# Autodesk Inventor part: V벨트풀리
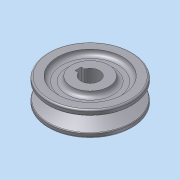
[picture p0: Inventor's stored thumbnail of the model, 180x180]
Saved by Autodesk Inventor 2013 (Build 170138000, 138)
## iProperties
Created: 2015-03
Part Number: V벨트풀리
Material: 강
Document SubType Name: Modeling
Designer: KYOUNG IL JANG
Density: 1 g/cm^3
CustomPartVersion: 1
Author: KYOUNG IL JANG
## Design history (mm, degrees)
sketch "주 스케치"
  geometry: L1 (0, 16)-(27, 16); L2 (27, 16)-(27, 12.861); L3 (27, 12.861)-(16, 9.498); L4 (16, 9.498)-(16, 6.502); L5 (16, 6.502)-(27, 3.139); L6 (27, 3.139)-(27, 0); L7 (27, 0)-(0, 0); L8 (25, 12.25)-(25, 3.75); L9 (16, 8)-(25, 8); L10 (27, 12.861)-(27, 3.139); L11 (0, -3)-(0, 18) reference; L12 (0, 0)-(0, 16)
  constraints: 22 end point, 5 perpendicular, 2 collinear, 2 midpoint, 2 point on line, 1 parallel
  dimensions: "d0" = 8.5 distance of L8.start L8.end (= da_Bw); "d1" = 34 deg angle of L3 L5 (= da_Alfa); "d2" = 2 distance between parallel lines of L2 L8 (= da_c); "d6" = 16 distance between parallel lines of L7 L1 (computed from d5, da_ng, da_Sg); "d21" = 50 diameter of L8 L11 (= da_Dw); "d25" = 11 distance between parallel lines of L4 L10 (= da_Hd); "d27" = 8 distance between parallel lines of L7 L9 (= da_Se)
node "벨트 평면"
revolve "본체" stored, may be unused: angle "d7" = 90 deg
revolve "그루브" stored, may be unused: angle "d15" = 90 deg
feature "허브 키홈"
fillet "모깎기3" dims "d28" = 0.5, "d29" = 1, "d30" = 1
sketch "스케치2"
  geometry: C1 r 12 at (0, 0); C2 r 21 at (0, 0); 1 further point
  constraints: 2 centre point, 2 coincident
  dimensions: "d31" = 24 diameter of C1; "d32" = 42 diameter of C2
extrude "돌출1" cut sketch "스케치2" distance "d33" = 3; taper "d34" = 0 deg
fillet "모깎기4" dims "d35" = 3
node "작업 평면2"
body "Solid1"
pattern_linear "그루브 패턴" dims "d18" = 12 (= da_Sg)
mirror "대칭1"
other parameters: "d5" = 8 (= da_Se), "da_Bw" = 8.5 [user parameter; used in 1 equation term], "da_Alfa" = 34 deg [user parameter; used in 1 equation term], "da_c" = 2 [user parameter; used in 1 equation term], "da_Dw" = 50 [user parameter; used in 1 equation term], "da_Hd" = 11 [user parameter; used in 1 equation term], "da_Se" = 8 [user parameter; used in 2 equation terms], "da_Sg" = 12 [user parameter; used in 2 equation terms], "da_r1" = 0 [user parameter], "da_r2" = 0 [user parameter], "d24" = 0, "d26" = 0
